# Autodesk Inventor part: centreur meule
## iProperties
Shininess: 64.0
Length Units: 11269
Angle Units: 11279
Time Units: 11290
Mass Units: 11283
Length Display Precision: 3
Angle Display Precision: 2
Compacted: True
Part Number: centreur meule
Document SubType Name: Modeling
Created: 2005-01
Material: Par défaut
Designer: LEGERET Philippe
Density: 0.0
Volumn: 0.0
Area: 0.0
PropertySet Name: Model Information
Control State: 0
Master: False
Checked Out: False
Author: LEGERET Philippe
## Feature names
1. Révolution1 [Revolution]
2. Perçage1 [Hole]
3. Réseau circulaire1 [Circular Pattern]
